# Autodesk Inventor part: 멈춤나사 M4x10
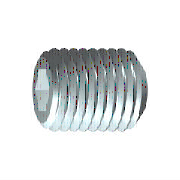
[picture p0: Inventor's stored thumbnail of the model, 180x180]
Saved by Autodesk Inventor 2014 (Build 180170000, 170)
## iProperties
Created: 2012-02
Part Number: 멈춤나사 M4x10
Material: 강철, 연강
Description: 6각 소켓 머리 없는 멈춤 나사
Document SubType Name: Modeling
Standard: KS B 1028
Designer: mduedu
Standards Organization: KS
Language: ko-KR
Size Designation: 납작점M4x10
Categories: <MemberInstance><Categories><Category DisplayName="조임쇠" InternalName="e4da775c-781d-43d5-af7c-5136215cf5a6" Mnemonic="FSTN"><Category DisplayName="볼트" InternalN
Density: 1 g/cm^3
Appearance: Steel
IsCustomPart: 1
Author: mduedu
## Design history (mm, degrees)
sketch "스케치1"
  geometry: L1 (0, 0)-(6.833, 0); L2 (10, 1.155)-(10, 2); L3 (10, 2)-(0, 2); L4 (10, 1.155)-(7.5, 1.155); L5 (7.5, 1.155)-(6.833, 0); L6 (0, -0.4)-(0, 2.4) reference; L7 (0, 2)-(0, 0)
  constraints: 13 end point, 3 parallel, 1 collinear, 1 perpendicular, 1 point on line
  dimensions: "d0" = 2.5 distance of L2.start L4.end (= INTI); "d1" = 60 deg angle of L5 L1; "d2" = 4 diameter of L3 L1 (= NND); "d3" = 2.3094 diameter of L4 L1 (= 1.1547 x SW); "d5" = 10 distance from line of L2 L3.end (= NLG)
revolve "본체" sketch "스케치1" stored, may be unused: angle "d6" = 90 deg
sketch "스케치2"
  geometry: L1 (-0.577, 1)-(0.577, 1); L2 (0.577, 1)-(1.155, 0); L3 (1.155, 0)-(0.577, -1); L4 (0.577, -1)-(-0.577, -1); L5 (-0.577, -1)-(-1.155, 0); L6 (-1.155, 0)-(-0.577, 1); A1 r 1.155 centre (0, 0) between (-0.577, 1) and (0.577, 1) reference; 2 further points
  constraints: 12 end point, 2 point on circle, 1 coincident, 1 horizontal, 11 other
extrude "슬롯" join sketch "스케치2" taper "d9" = 0 deg; stored distance "d21" = 10
workaxis "Work Axis1"
workplane "Work Plane1"
workaxis "Work Axis2"
body "Solid1"
chamfer "모따기1" distance "d7" = 0.42941 (= -0.5 x GD1 + 0.5 x NND); stored, may be unused: angle "d8" = 45 deg (= FAWI), second distance "d29" = 0.42941 (= -0.5 x GD1 + 0.5 x NND)
feature "스레드" dims "d11" = 10 (= NLG), "d12" = 0
chamfer "모따기2" distance "d13" = 0.42941 (= -0.5 x GD1 + 0.5 x NND); stored, may be unused: angle "d14" = 45 deg (= FAWI), second distance "d30" = 0.42941 (= -0.5 x GD1 + 0.5 x NND)
other parameters: "NND" = 4 [user parameter; used in 5 equation terms], "NLG" = 10 [user parameter; used in 2 equation terms], "INTI" = 2.5 [user parameter; used in 1 equation term], "FAWI" = 45 deg [user parameter; used in 2 equation terms], "SW" = 2 [user parameter; used in 2 equation terms], "GD1" = 3.14117 (= THREADDIA - 1.2269 x PTC) [user parameter; used in 4 equation terms], "d4" = 0, "FAWI1" = 45 deg [user parameter], "d15" = 0, "d31" = 0, "GUL" = 0.42941 (= 0.61345 x PTC) [user parameter], "SPD" = 2.5 [user parameter], "TPU" = 14.28571 (computed from PTC) [user parameter], "TOA" = 30 deg [user parameter], "THREADDIA" = 4 [user parameter; used in 1 equation term], "PTC" = 0.7 [user parameter; used in 4 equation terms], "GAL" = 0.42941 (= 0.61345 x PTC) [user parameter], "E0" = 2.31 (= 1.155 x SW) [user parameter]
